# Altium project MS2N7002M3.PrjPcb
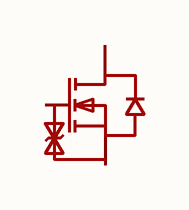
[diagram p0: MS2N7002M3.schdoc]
1 sheet, 1 parts. Net scope: global (net labels, ports and power ports of the same name join across sheets).

## Sheet MS2N7002M3.schdoc
size 127 x 101 mm

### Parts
Q?  ms2n7002m3  [SOT-723-3_L1.2-W0.8-LS1.20-BR]  (value not drawn)

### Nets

Not connected (* = marked no-connect by the designer): Q? 1(G) 2(S) 3(D)

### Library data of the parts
Q? = ms2n7002m3: 数量:1个N沟道;漏源电压(Vdss):60V;连续漏极电流(Id):340mA;导通电阻(RDS(on)):4Ω@10V;耗散功率(Pd):150mW;阈值电压(Vgs(th)):1.4V;; Manufacturer: MSKSEMI(美森科); AddInBom: yes; ModelId: abccde1e67074d7481274a37cf5c97f0; ModelName: SOT-723-3P_L1.2-W0.8-H0.6-LS1.2-P0.40; ModelTransform: 47.244,47.244,0,180,0,0,-0.004,0,0; Number: 1个N沟道; Drain to Source Voltage: 60V; Current - Continuous Drain(Id): 340mA; RDS(on): 4Ω@10V; Pd - Power Dissipation: 150mW; Gate Threshold Voltage (Vgs(th)): 1.4V; Gate Charge(Qg): 30nC@25V; Input Capacitance(Ciss): 40pF; Reverse Transfer Capacitance (Crss@Vds): 10pF; Output Capacitance(Coss): 30pF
